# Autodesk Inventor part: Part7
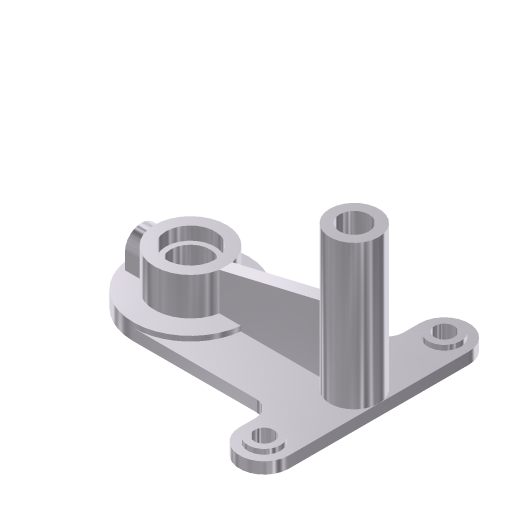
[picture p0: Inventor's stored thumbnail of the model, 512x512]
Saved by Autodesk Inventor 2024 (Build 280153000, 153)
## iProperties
Shininess: 77.0
Length Units: 11269
Angle Units: 11279
Time Units: 11290
Mass Units: 11283
Length Display Precision: 3
Angle Display Precision: 2
Created: 2001-12
Part Number: Part7
Document SubType Name: Modeling
Density: 1 g/cm^3
Material: Generic
Appearance: Metal-AL-6061 (Polished)
Density: 0.0
Volumn: 0.0
Area: 0.0
PropertySet Name: Model Information
Control State: 0
Master: False
Checked Out: False
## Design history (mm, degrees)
sketch "Sketch1"
  geometry: L1 (46.121, -53.4)-(46.121, 56.6); L2 (16.121, 56.6)-(16.121, 36.6); L3 (16.121, 36.6)-(-68.879, 36.6); L4 (-68.879, -33.4)-(16.121, -33.4); L5 (16.121, -33.4)-(16.121, -53.4); A1 r 15 centre (31.121, 56.6) between (46.121, 56.6) and (16.121, 56.6); A2 r 35 centre (-68.879, 1.6) between (-68.879, 36.6) and (-68.879, -33.4); A3 r 15 centre (31.121, -53.4) between (16.121, -53.4) and (46.121, -53.4)
  constraints: 10 end point, 6 point on circle, 5 tangent, 3 centre point, 3 parallel, 2 equal length, 1 equal radius, 1 perpendicular, 1 vertical
  dimensions: "d0" = 15 radius of A1; "d1" = 110 distance of L1.start L1.end; "d2" = 100 horizontal distance of A3.centre A2.centre; "d3" = 35 radius of A2
extrude "Extrusion1" new body sketch "Sketch1" distance "d4" = 7; taper "d5" = 0 deg
sketch "Sketch2"
  geometry: C1 r 10 at (31.121, 56.6); C2 r 10 at (31.121, -53.4); C3 r 35 at (-68.879, 1.6); A1 r 35 centre (-68.879, 1.6) between (-68.879, 36.6) and (-68.879, -33.4) reference; A2 r 15 centre (31.121, 56.6) between (46.121, 56.6) and (16.121, 56.6) reference; A3 r 15 centre (31.121, -53.4) between (16.121, -53.4) and (46.121, -53.4) reference
  constraints: 3 centre point, 3 concentric, 2 equal radius
  dimensions: "d45" = 20 diameter of C1
extrude "Extrusion2" join sketch "Sketch2" distance "d6" = 3; taper "d7" = 0 deg
sketch "Sketch3"
  geometry: C1 r 22 at (0, 0); 1 further point
  constraints: 1 centre point, 1 coincident
  dimensions: "d8" = 44 diameter of C1
extrude "Extrusion3" join sketch "Sketch3" distance "d9" = 23; taper "d10" = 0 deg
sketch "Sketch4"
  geometry: L1 (46.121, 56.6)-(46.121, -53.4) reference; L2 (-68.879, 36.6)-(16.121, 36.6) reference; C1 r 15 at (31.121, 1.6)
  constraints: 1 centre point
  dimensions: "d11" = 30 diameter of C1; "d12" = 15 distance from line of L1 C1.centre; "d13" = 35 distance from line of L2 C1.centre
extrude "Extrusion4" join sketch "Sketch4" distance "d14" = 88; taper "d15" = 0 deg
workplane "Work Plane1"
feature "Rib1" dims "d21" = 1, "d22" = 8
workplane "Work Plane2"
workplane "Work Plane3"
sketch "Sketch7"
  geometry: L1 (10, 0)-(10, 10); L2 (-10, 10)-(-10, 0); L3 (-10, 0)-(10, 0); L4 (55, -10)-(55, -3) reference; A1 r 10 centre (0, 10) between (10, 10) and (-10, 10); 2 further points
  constraints: 6 end point, 2 point on circle, 2 tangent, 1 centre point, 1 parallel, 1 perpendicular, 1 vertical
  dimensions: "d30" = 10 radius of A1; "d34" = 55 distance from line of L4 A1.centre; "d35" = 10 distance of L1.start L1.end
extrude "Extrusion6" join sketch "Sketch7" stored distance "d36" = 88; taper "d37" = 0 deg
sketch "Sketch8"
  geometry: C1 r 10 at (0, 0) reference
hole "Hole1" sketch "Sketch8" diameter "d38" = 12; stored, may be unused: countersink angle "d42" = 82 deg, drill point angle "d44" = 118 deg; dims "d39" = 6, "d40" = 4, "d41" = 2, "d43" = 8
mirror "Mirror1"
sketch "Sketch9"
  geometry: C1 r 10 at (0, 0)
  constraints: 1 centre point
hole "Hole2" sketch "Sketch9" at (0, 0) diameter "d52" = 18; stored, may be unused: drill point angle "d47" = 118 deg, countersink angle "d48" = 82 deg; dims "d46" = 6, "d49" = 2, "d50" = 4, "d51" = 8
sketch "Sketch10"
  geometry: C1 r 10 at (0, 0)
  constraints: 1 centre point
hole "Hole3" sketch "Sketch10" at (0, 0) diameter "d59" = 24; stored, may be unused: drill point angle "d54" = 118 deg, countersink angle "d55" = 82 deg; dims "d53" = 6, "d56" = 8, "d57" = 30, "d58" = 8
sketch "Sketch11"
  geometry: C1 r 10 at (0, 0)
  constraints: 1 centre point
hole "Hole4" sketch "Sketch11" at (0, 0) diameter "d66" = 10; stored, may be unused: drill point angle "d61" = 0 deg, countersink angle "d62" = 82 deg; dims "d60" = 6, "d63" = 2, "d64" = 4, "d65" = 8
fillet "Fillet1" dims "d67" = 10
body "Solid1"
sketch "Sketch5"
  geometry: L1 (22, 33.1)-(85, 48); L2 (0, 7)-(35, 7) reference; L3 (85, 0)-(85, 7) reference; L4 (115, 0)-(115, 7) reference; L5 (115, 0)-(85, 0) reference
  constraints: 2 end point
  dimensions: "d17" = 26.1 distance from line of L2 L1.start; "d18" = 63 distance from line of L3 L1.start; "d19" = 30 distance from line of L4 L1.end; "d20" = 48 distance from line of L5 L1.end
other parameters: "d16" = -35, "d29" = -8
